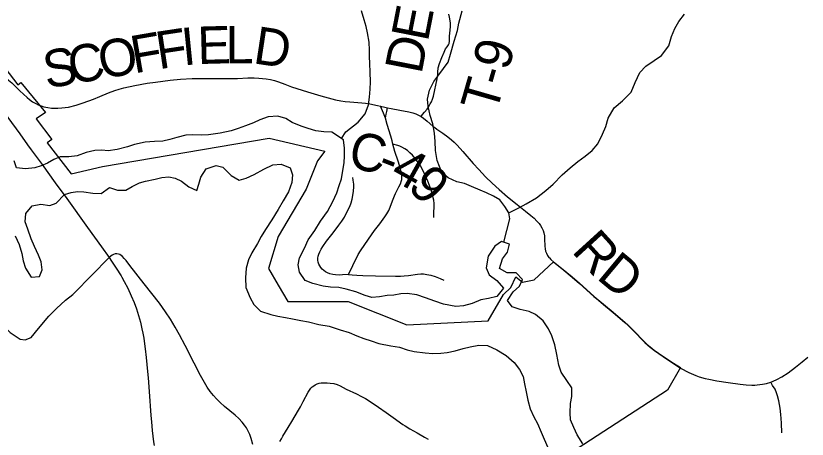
# Model space of a CAD drawing. Extents: x 0 to 34, y 0 to 22.
# Drawn here: x 6.068 to 7.268, y 15.361 to 16.003 of the extents above; entities that cross this region are included whole.
import ezdxf

# ---------------------------------------------------------------- set-up
doc = ezdxf.new("R2010")
doc.units = 0
for name, color, linetype in [('GM_X_City_Street', 7, 'Continuous'), ('GM_X_Corporation', 7, 'Continuous'), ('GM_X_County_Road', 7, 'Continuous'), ('GM_X_County_Road_Text', 7, 'Continuous'), ('GM_X_Minor_River', 7, 'Continuous'), ('GM_X_Township_Road', 7, 'Continuous'), ('GM_X_Township_Road_Text', 7, 'Continuous'), ('GM_X_US_Route', 7, 'Continuous')]:
    doc.layers.add(name, color=color, linetype=linetype)

msp = doc.modelspace()

# ---------------------------------------------------------------- linework, layer by layer
at = {"layer": 'GM_X_City_Street'}
for points in [[(5.9554, 15.5715), (5.9581, 15.5715), (5.9639, 15.5726), (5.9727, 15.5803), (5.9827, 15.5861), (5.9896, 15.5864), (5.9957, 15.5826), (6.003, 15.5746), (6.0126, 15.565), (6.0428, 15.5385), (6.0593, 15.5228), (6.0742, 15.5129), (6.0819, 15.5117), (6.0907, 15.5152), (6.1022, 15.529), (6.1176, 15.5477), (6.1294, 15.5596), (6.1428, 15.5719), (6.1543, 15.5807), (6.185, 15.6121), (6.2068, 15.6343), (6.2091, 15.6368)], [(6.4681, 15.3577), (6.4709, 15.3618), (6.473, 15.3656), (6.4811, 15.3787), (6.4864, 15.3878), (6.4966, 15.4052), (6.4994, 15.41), (6.5038, 15.4182), (6.5112, 15.4325), (6.5131, 15.4356), (6.5151, 15.4385), (6.5175, 15.4406), (6.5197, 15.4422), (6.5221, 15.4436), (6.5247, 15.4449), (6.5279, 15.446), (6.5309, 15.4466), (6.534, 15.4469), (6.5399, 15.4468), (6.5447, 15.4462), (6.5503, 15.4454), (6.5551, 15.4441), (6.56, 15.4421), (6.5643, 15.4398), (6.569, 15.4371), (6.5847, 15.43), (6.5924, 15.4261), (6.5983, 15.4228), (6.604, 15.4191), (6.6178, 15.4098), (6.6297, 15.4019), (6.6403, 15.3943), (6.6548, 15.3836), (6.6584, 15.3812), (6.6653, 15.3771), (6.6767, 15.3707), (6.6878, 15.364), (6.6933, 15.361)]]:
    msp.add_lwpolyline(points, dxfattribs=at)
at = {"layer": 'GM_X_Corporation'}
msp.add_lwpolyline([(6.036, 15.9439), (6.0707, 15.8988), (6.0752, 15.9023), (6.1128, 15.8565), (6.0987, 15.8473), (6.1225, 15.8155), (6.1154, 15.8107), (6.1514, 15.7639), (6.1991, 15.775), (6.4522, 15.818), (6.5366, 15.7981), (6.5255, 15.7832), (6.5084, 15.7406), (6.4658, 15.6686), (6.4511, 15.6199), (6.4656, 15.5949), (6.4802, 15.5698), (6.572, 15.5702), (6.6608, 15.5346), (6.7846, 15.5409), (6.8077, 15.5807), (6.8187, 15.5913), (6.8264, 15.6076), (6.8363, 15.5995), (6.8542, 15.603), (6.8838, 15.6302), (6.8958, 15.6205), (6.9117, 15.6074), (6.923, 15.5977), (6.9447, 15.5783), (6.9484, 15.575), (6.9593, 15.5658), (6.9741, 15.5536), (6.9917, 15.5388), (6.9967, 15.5341), (7.0038, 15.5271), (7.0219, 15.5084), (7.0259, 15.5046), (7.0302, 15.5011), (7.0365, 15.4961), (7.043, 15.4915), (7.0549, 15.4836), (7.0657, 15.4763), (7.0762, 15.4697), (7.0565, 15.4356), (6.911, 15.3408)], dxfattribs=at)
at = {"layer": 'GM_X_County_Road'}
for points in [[(6.0413, 15.919), (6.0484, 15.913), (6.0568, 15.9057), (6.0614, 15.9015), (6.0677, 15.8956), (6.074, 15.8896), (6.0848, 15.8794), (6.0886, 15.8763), (6.093, 15.873), (6.0978, 15.8702), (6.1016, 15.8683), (6.1061, 15.8666)], [(6.1061, 15.8666), (6.1102, 15.8654), (6.1163, 15.8642), (6.1217, 15.8634), (6.1266, 15.8632), (6.1315, 15.8632), (6.1377, 15.8637), (6.1475, 15.8648), (6.1593, 15.8678), (6.1699, 15.8713), (6.1856, 15.8771), (6.1954, 15.8811), (6.2085, 15.8867), (6.2179, 15.8902), (6.2244, 15.8923), (6.2317, 15.8941), (6.2482, 15.8975), (6.2671, 15.901), (6.2794, 15.9028), (6.3017, 15.9055), (6.3178, 15.9071), (6.3351, 15.9082), (6.3457, 15.9085), (6.3749, 15.9084), (6.3904, 15.9083), (6.4041, 15.9085), (6.4195, 15.9092), (6.4295, 15.9093), (6.4364, 15.909), (6.4475, 15.9078), (6.4543, 15.9066), (6.4604, 15.9051), (6.4664, 15.9032), (6.4757, 15.8998), (6.4862, 15.8958), (6.5103, 15.888), (6.5305, 15.8819), (6.5473, 15.8772), (6.5527, 15.8759), (6.5611, 15.8743), (6.5672, 15.8734), (6.5746, 15.8727), (6.5926, 15.8714), (6.5982, 15.8708), (6.605, 15.8698), (6.6166, 15.8675), (6.6212, 15.8663)], [(6.6212, 15.8663), (6.6275, 15.8648), (6.6318, 15.8638), (6.6371, 15.8626), (6.6505, 15.8601), (6.664, 15.8577), (6.6701, 15.8562), (6.6749, 15.8546), (6.6789, 15.8529), (6.6826, 15.8507)], [(6.6826, 15.8507), (6.6864, 15.8481), (6.6917, 15.8437), (6.7007, 15.8361), (6.7035, 15.8338), (6.7065, 15.8315), (6.7156, 15.8251), (6.7232, 15.8196), (6.7286, 15.8153), (6.7328, 15.8116), (6.7373, 15.8072), (6.746, 15.7975), (6.7619, 15.7792), (6.7702, 15.77), (6.7805, 15.7593), (6.7907, 15.7494), (6.8012, 15.7397), (6.8139, 15.7288), (6.8282, 15.717), (6.841, 15.7071), (6.8493, 15.7006), (6.854, 15.6965), (6.8585, 15.6921), (6.8618, 15.6882), (6.864, 15.6852), (6.8659, 15.6819), (6.8677, 15.6778), (6.8688, 15.6741), (6.8697, 15.6698), (6.87, 15.6653), (6.8703, 15.6542), (6.8707, 15.65), (6.8716, 15.6464), (6.8728, 15.6431), (6.8745, 15.6399), (6.8766, 15.637), (6.8773, 15.6362)], [(6.4273, 15.3532), (6.4247, 15.3622), (6.4227, 15.3681), (6.4203, 15.3733), (6.4176, 15.3783), (6.4148, 15.3825), (6.4113, 15.3869), (6.4061, 15.3924), (6.4006, 15.3975), (6.3844, 15.411), (6.3779, 15.4167), (6.3722, 15.4223), (6.3676, 15.4274), (6.3626, 15.4336), (6.358, 15.4402), (6.3538, 15.447), (6.3478, 15.4578), (6.3382, 15.4766), (6.3247, 15.5032), (6.316, 15.5197), (6.3097, 15.5311), (6.3022, 15.5433), (6.295, 15.5542), (6.2856, 15.5674), (6.2626, 15.5968), (6.2408, 15.6246), (6.2351, 15.632), (6.2323, 15.6354), (6.2296, 15.6382), (6.2276, 15.6398), (6.2253, 15.6411), (6.2234, 15.6417), (6.2208, 15.6421), (6.2182, 15.6421), (6.2158, 15.6414), (6.2137, 15.6403), (6.2118, 15.6389), (6.2091, 15.6368)], [(6.8773, 15.6362), (6.8794, 15.6338), (6.884, 15.6297), (6.8961, 15.62), (6.9119, 15.6069), (6.9232, 15.5972), (6.9449, 15.5778), (6.9486, 15.5745), (6.9595, 15.5653), (6.9743, 15.5531), (6.9919, 15.5382), (6.9969, 15.5336), (7.004, 15.5266), (7.0221, 15.5079), (7.0261, 15.5041), (7.0304, 15.5006), (7.0367, 15.4956), (7.0433, 15.491), (7.0551, 15.4831), (7.0659, 15.4758), (7.0764, 15.4691)], [(7.2131, 15.4475), (7.2171, 15.449), (7.2227, 15.4515), (7.2301, 15.4558), (7.2394, 15.4619), (7.2509, 15.4702), (7.2611, 15.4783), (7.2696, 15.4855)], [(7.0764, 15.4691), (7.0888, 15.4623), (7.0995, 15.4577), (7.1048, 15.4559), (7.1137, 15.4534), (7.1191, 15.4521), (7.1313, 15.4499), (7.1484, 15.4472), (7.1669, 15.4447), (7.1761, 15.4437), (7.1847, 15.4432), (7.189, 15.4432), (7.1927, 15.4435), (7.2006, 15.4445), (7.2066, 15.4457), (7.2131, 15.4475)]]:
    msp.add_lwpolyline(points, dxfattribs=at)
at = {"layer": 'GM_X_Minor_River'}
for points in [[(6.5618, 15.8172), (6.5682, 15.8276), (6.5874, 15.8418), (6.5978, 15.8549), (6.603, 15.8681), (6.6046, 15.8799), (6.6052, 15.892), (6.6057, 15.903), (6.6056, 15.9179), (6.605, 15.9308), (6.6044, 15.9418), (6.6042, 15.9513), (6.6036, 15.9635), (6.6015, 15.9776), (6.5994, 15.9871), (6.5965, 15.9974), (6.5921, 16.0111)], [(6.8081, 15.66), (6.8173, 15.6952), (6.8156, 15.7047), (6.8096, 15.7143), (6.8022, 15.7242), (6.7924, 15.7297), (6.7819, 15.7348), (6.7721, 15.7387), (6.7593, 15.7443), (6.7487, 15.749), (6.737, 15.7514), (6.7238, 15.7577), (6.7141, 15.7658), (6.7068, 15.7838), (6.7047, 15.799), (6.7038, 15.8127), (6.7032, 15.8252), (6.7007, 15.8397), (6.6964, 15.8519), (6.6932, 15.8664), (6.6926, 15.8767), (6.6954, 15.8907), (6.7021, 15.9039), (6.7094, 15.914), (6.7237, 15.9332), (6.7273, 15.9453), (6.7329, 15.965), (6.7377, 15.9812), (6.7397, 15.9922), (6.7449, 16.0108)], [(6.8156, 15.7047), (6.832, 15.7124), (6.8423, 15.718), (6.8576, 15.7272), (6.8718, 15.7384), (6.8833, 15.7481), (6.8968, 15.762), (6.9087, 15.7728), (6.9206, 15.7825), (6.9317, 15.7903), (6.9421, 15.7993), (6.9506, 15.809), (6.958, 15.8238), (6.9631, 15.8355), (6.9663, 15.8479), (6.9756, 15.8638), (6.9883, 15.8742), (7.0014, 15.8877), (7.0076, 15.902), (7.0147, 15.9175), (7.0239, 15.9272), (7.0362, 15.9358), (7.0473, 15.9432), (7.0585, 15.9579), (7.0625, 15.9719), (7.0676, 15.984), (7.0738, 15.9945), (7.0823, 16.0061)], [(6.8811, 15.518), (6.8759, 15.5287), (6.8678, 15.5406), (6.8562, 15.5502), (6.8464, 15.5549), (6.8331, 15.5578), (6.8207, 15.5621), (6.814, 15.5717), (6.8222, 15.5849), (6.8318, 15.5931), (6.8365, 15.6033), (6.8267, 15.6137), (6.8135, 15.6135), (6.8014, 15.6202), (6.8062, 15.6349), (6.8136, 15.6447), (6.8168, 15.6572), (6.8047, 15.6612), (6.7947, 15.6537), (6.7843, 15.639), (6.7814, 15.6212), (6.7858, 15.6105), (6.7978, 15.602), (6.8078, 15.5901), (6.7978, 15.5777), (6.7849, 15.5748), (6.7734, 15.5727), (6.7601, 15.5668), (6.7472, 15.5636), (6.7354, 15.5626), (6.7165, 15.566), (6.7036, 15.5703), (6.6893, 15.5755), (6.6761, 15.5802), (6.6613, 15.582), (6.6519, 15.5814), (6.6412, 15.5796), (6.631, 15.579), (6.6196, 15.5773), (6.6078, 15.5763), (6.5976, 15.5791), (6.5837, 15.5846), (6.5689, 15.5886), (6.5576, 15.5911), (6.5451, 15.592), (6.5341, 15.5933), (6.5186, 15.5974), (6.5069, 15.6017), (6.498, 15.6144), (6.4959, 15.6258), (6.498, 15.6364), (6.5058, 15.6507), (6.5113, 15.6636), (6.5213, 15.6775), (6.5299, 15.6918), (6.5407, 15.7064), (6.5489, 15.7215), (6.5548, 15.7347), (6.5583, 15.7461), (6.5619, 15.7559), (6.5636, 15.7658), (6.5657, 15.7802), (6.5666, 15.7912), (6.5664, 15.8026), (6.565, 15.8151), (6.5474, 15.8268), (6.5353, 15.8273), (6.5231, 15.829), (6.5111, 15.8322), (6.5005, 15.8358), (6.4869, 15.8417), (6.4772, 15.8476), (6.4651, 15.8512), (6.4506, 15.8499), (6.4377, 15.8455), (6.4281, 15.8411), (6.4163, 15.8363), (6.4053, 15.8323), (6.3942, 15.829), (6.3775, 15.8251), (6.36, 15.8227), (6.3501, 15.8225), (6.3357, 15.8227), (6.3255, 15.8221), (6.3122, 15.8188), (6.3015, 15.8159), (6.2909, 15.8134), (6.2783, 15.8125), (6.2639, 15.8119), (6.2476, 15.808), (6.2373, 15.8047), (6.2217, 15.8004), (6.208, 15.7987), (6.1981, 15.7996), (6.1875, 15.799), (6.1746, 15.7958), (6.1609, 15.791), (6.1483, 15.7897), (6.1351, 15.7895), (6.1251, 15.7855), (6.1156, 15.7799)], [(6.1156, 15.7799), (6.106, 15.7759), (6.0965, 15.7726), (6.0825, 15.7713), (6.0688, 15.7726), (6.0652, 15.7833)], [(6.1414, 15.7321), (6.1517, 15.7353), (6.1612, 15.7367), (6.1711, 15.7362), (6.1843, 15.7341), (6.1972, 15.7339), (6.2098, 15.7428), (6.2219, 15.7389), (6.2344, 15.7391), (6.2444, 15.7442), (6.2551, 15.7501), (6.2646, 15.7527), (6.279, 15.7555), (6.2893, 15.758), (6.2996, 15.759), (6.3094, 15.7573), (6.3192, 15.7526), (6.33, 15.7437), (6.3421, 15.7382), (6.3453, 15.7481), (6.3485, 15.7587), (6.3566, 15.7715), (6.3715, 15.7762), (6.3817, 15.7737), (6.3944, 15.761), (6.4068, 15.754), (6.4171, 15.7573), (6.4293, 15.7628), (6.4438, 15.7709), (6.4576, 15.7772), (6.4701, 15.7785), (6.484, 15.7726), (6.4873, 15.7623), (6.4864, 15.7506), (6.4816, 15.7362), (6.4734, 15.7226), (6.4657, 15.7094), (6.456, 15.694), (6.4463, 15.679), (6.44, 15.6684), (6.4346, 15.6582), (6.4257, 15.6439), (6.4209, 15.633), (6.4173, 15.6205), (6.416, 15.6057), (6.4169, 15.5913), (6.4231, 15.5756), (6.4287, 15.5656), (6.4388, 15.5552), (6.4546, 15.5501), (6.4652, 15.548), (6.4769, 15.5459), (6.4875, 15.5439), (6.5, 15.5414), (6.5117, 15.539), (6.5276, 15.5353), (6.5431, 15.5324), (6.5597, 15.5269), (6.5737, 15.5229), (6.5853, 15.5181), (6.5959, 15.5138), (6.6068, 15.5102), (6.6185, 15.5062), (6.6367, 15.5026), (6.6499, 15.5005), (6.6616, 15.4969), (6.6722, 15.4944), (6.6889, 15.4923), (6.7006, 15.491), (6.7127, 15.4916), (6.7222, 15.4926), (6.7344, 15.4954), (6.7466, 15.4987), (6.7572, 15.5012), (6.7705, 15.504), (6.7834, 15.5034), (6.7974, 15.4968), (6.8116, 15.4882), (6.824, 15.4774), (6.8322, 15.467), (6.8373, 15.4563), (6.8398, 15.4449), (6.8419, 15.4331), (6.8444, 15.4205), (6.8484, 15.4071), (6.8539, 15.3953), (6.8591, 15.3849), (6.8649, 15.3719), (6.8759, 15.346)], [(6.0666, 15.6697), (6.0728, 15.6563), (6.0768, 15.643), (6.0789, 15.6315), (6.0822, 15.6208), (6.0907, 15.6067), (6.1036, 15.608), (6.1075, 15.6182), (6.1062, 15.63), (6.1022, 15.6403), (6.0959, 15.6533), (6.0912, 15.6652), (6.0857, 15.6797), (6.0817, 15.6908), (6.083, 15.7037), (6.0926, 15.7153), (6.1056, 15.7178), (6.1192, 15.7157), (6.1291, 15.7193), (6.1414, 15.7321)], [(6.928, 15.3543), (6.9195, 15.3677), (6.9143, 15.3788), (6.9096, 15.3907), (6.9086, 15.4009), (6.9095, 15.4154), (6.9112, 15.426), (6.9114, 15.4393), (6.904, 15.4504), (6.8951, 15.463), (6.8918, 15.4737), (6.8886, 15.4897), (6.8858, 15.5042), (6.8811, 15.518)]]:
    msp.add_lwpolyline(points, dxfattribs=at)
at = {"layer": 'GM_X_Township_Road'}
for points in [[(6.6826, 15.8507), (6.6849, 15.8536), (6.6879, 15.8571), (6.6917, 15.862), (6.6942, 15.8656), (6.6966, 15.8696), (6.6984, 15.8729), (6.7001, 15.8769), (6.7015, 15.8816), (6.7071, 15.9077), (6.7077, 15.9107), (6.708, 15.915), (6.708, 15.92), (6.7083, 15.9224), (6.7087, 15.9242), (6.7106, 15.9308), (6.7141, 15.9401), (6.7176, 15.9483), (6.7197, 15.9531), (6.7221, 15.9565), (6.724, 15.9591), (6.7251, 15.9616), (6.7256, 15.9648), (6.7259, 15.9723), (6.7267, 15.9818), (6.7271, 15.987), (6.7272, 15.9923), (6.7268, 15.9957), (6.7255, 16.0011), (6.7247, 16.006)], [(6.5724, 15.611), (6.579, 15.6246), (6.5873, 15.6411), (6.5908, 15.6469), (6.6026, 15.6644), (6.612, 15.6775), (6.6199, 15.6879), (6.6278, 15.6983), (6.6308, 15.7029), (6.6335, 15.7078), (6.6358, 15.7129), (6.6394, 15.7227), (6.6424, 15.7301), (6.6437, 15.7336), (6.6458, 15.7381), (6.649, 15.7441), (6.6518, 15.7496), (6.6526, 15.7519), (6.6533, 15.7549), (6.6534, 15.758), (6.6533, 15.7611), (6.6525, 15.766), (6.6512, 15.7714), (6.6476, 15.7827), (6.643, 15.7975), (6.6399, 15.8087), (6.6385, 15.8137), (6.6365, 15.8208), (6.6313, 15.8387), (6.6288, 15.8483), (6.6257, 15.8555), (6.6242, 15.8591), (6.6212, 15.8663)], [(6.6288, 15.8483), (6.6298, 15.8541), (6.6305, 15.8583), (6.6318, 15.8638)], [(6.7019, 15.6972), (6.7019, 15.6996), (6.7022, 15.7046), (6.7027, 15.7139), (6.7026, 15.7189), (6.7018, 15.7238), (6.7006, 15.7293), (6.6982, 15.7377), (6.6928, 15.7523), (6.6885, 15.7626), (6.6853, 15.7693), (6.6818, 15.7759), (6.6784, 15.7811), (6.6743, 15.7866), (6.6698, 15.7918), (6.6658, 15.7957), (6.662, 15.7989), (6.658, 15.8018), (6.6536, 15.8042), (6.6502, 15.8057), (6.6472, 15.8066), (6.6399, 15.8087)], [(6.5724, 15.611), (6.5634, 15.6104), (6.5584, 15.6102), (6.5528, 15.6105), (6.5485, 15.611), (6.5443, 15.6121), (6.5408, 15.6134), (6.5375, 15.6152), (6.535, 15.617), (6.5326, 15.619), (6.5306, 15.6214), (6.5289, 15.624), (6.5276, 15.6268), (6.5267, 15.6297), (6.5262, 15.6328), (6.5262, 15.6359), (6.5266, 15.639), (6.5274, 15.642), (6.5288, 15.6455), (6.5308, 15.6494), (6.5334, 15.6535), (6.5392, 15.6616), (6.5491, 15.6744), (6.5579, 15.6857), (6.5622, 15.6917), (6.5662, 15.6981), (6.5706, 15.7063), (6.5743, 15.7142), (6.5766, 15.7199), (6.5782, 15.7253), (6.5793, 15.7308), (6.5802, 15.7375), (6.5806, 15.7437), (6.5805, 15.7481), (6.5797, 15.7542), (6.5793, 15.758)], [(6.5724, 15.611), (6.5778, 15.6105), (6.5849, 15.6099), (6.5942, 15.6095), (6.6135, 15.6091), (6.6439, 15.6082), (6.6514, 15.6083), (6.657, 15.6087), (6.6637, 15.6096), (6.6772, 15.6116), (6.6822, 15.612), (6.6865, 15.6119), (6.6914, 15.6112), (6.6975, 15.6098), (6.704, 15.6078), (6.7115, 15.6049), (6.7173, 15.6024)], [(7.23, 15.3708), (7.2293, 15.3857), (7.2288, 15.3926), (7.2285, 15.3987), (7.2273, 15.4081), (7.2255, 15.4192), (7.2234, 15.4267), (7.2221, 15.4315), (7.2197, 15.4368), (7.216, 15.4428), (7.2131, 15.4475)]]:
    msp.add_lwpolyline(points, dxfattribs=at)
at = {"layer": 'GM_X_US_Route'}
for points in [[(6.0252, 15.891), (6.0277, 15.8875), (6.0343, 15.8784), (6.0484, 15.8587), (6.0682, 15.8317), (6.0736, 15.8241), (6.0856, 15.8075), (6.0911, 15.8001), (6.1075, 15.778), (6.1273, 15.7502), (6.1449, 15.7261), (6.1765, 15.6823), (6.1976, 15.6531), (6.2091, 15.6368)], [(6.2091, 15.6368), (6.2129, 15.6312), (6.2199, 15.6208), (6.2275, 15.6087), (6.2285, 15.6068)], [(6.2285, 15.6068), (6.2321, 15.6005), (6.2375, 15.59), (6.2428, 15.5787), (6.2472, 15.5684), (6.2507, 15.559), (6.2539, 15.5489), (6.2567, 15.5387), (6.2591, 15.5284), (6.2603, 15.522), (6.2617, 15.5143), (6.2628, 15.506), (6.2639, 15.4981), (6.2656, 15.485), (6.2677, 15.4636), (6.2684, 15.4544), (6.27, 15.4333), (6.2725, 15.3973), (6.2733, 15.3873), (6.2746, 15.3745), (6.2767, 15.3573), (6.2777, 15.3516)]]:
    msp.add_lwpolyline(points, dxfattribs=at)

# ---------------------------------------------------------------- texts
at = {"layer": 'GM_X_County_Road_Text'}
for s, rotation, p in [('F', 8.5796, (6.2847, 15.9222)), ('I', 5.7153, (6.3218, 15.9279)), ('E', 1.5452, (6.3439, 15.9301)), ('L', 0.1982, (6.3861, 15.9312)), ('D', 351.3698, (6.4263, 15.9316)), ('F', 9.7822, (6.2472, 15.9158)), ('C', 9.8033, (6.1519, 15.8993)), ('O', 9.8022, (6.1979, 15.9073)), ('S', 9.8009, (6.1142, 15.8928)), ('C', 348.4654, (6.5701, 15.7737)), ('4', 330.8636, (6.6333, 15.7574)), ('-', 338.5943, (6.6134, 15.7651)), ('9', 314.0414, (6.6604, 15.7431)), ('R', 312.3275, (6.9098, 15.6459)), ('D', 320.1418, (6.9472, 15.6057))]:
    msp.add_text(s, height=0.0568, rotation=rotation, dxfattribs=at).set_placement(p)
at = {"layer": 'GM_X_Township_Road_Text'}
for s, rotation, p in [('E', 78.9302, (6.6927, 15.9627)), ('D', 78.9562, (6.6831, 15.9136)), ('9', 75.5683, (6.8152, 15.9186)), ('T', 73.9024, (6.7964, 15.8536)), ('-', 73.9126, (6.8082, 15.8945))]:
    msp.add_text(s, height=0.0568, rotation=rotation, dxfattribs=at).set_placement(p)

doc.saveas('drawing.dxf')
